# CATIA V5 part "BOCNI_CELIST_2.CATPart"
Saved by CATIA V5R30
Part number: BOCNI_CELIST_2
Bounding box of the stored display mesh (mm): x -40 to 40, y -109.038 to -37.031, z -36.619 to -1.271
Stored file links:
  C:\Users\ondra\Desktop\PŘÍLOHA P III\CATIA\BOCNI_CELIST_2.CATPart
  C:\Users\ondra\Desktop\FORMA_BAKALARKA\Part1.CATPart
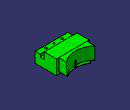
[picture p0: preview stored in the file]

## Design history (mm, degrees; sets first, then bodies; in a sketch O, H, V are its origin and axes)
Body1 (main body)
  Body2 "BOCNI TVARNIK 2"
    Solid1: linked copy from another document
  Assemble1: tool Body2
